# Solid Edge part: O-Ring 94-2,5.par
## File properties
Title: O-Ring 94-2,5
Author: Dan
Template: Normal Colour.par
Last saved by: Dan
Revision: 9
Application: Solid Edge
Density: 0 kg/mm^3
Accuracy: 0.99
Document Number: P52-009
Project Name: Piston Pump P52
Material: nitrile
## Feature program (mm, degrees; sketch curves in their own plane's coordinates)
sketch for "unnamed RevolvedProtrusion 1" plane through (0, 0, 0) normal (0, 0, 1) x-axis (1, 0, 0)
  circle centre (0, -48.25) radius 1.25
revolve "unnamed RevolvedProtrusion 1" add finite 360 deg
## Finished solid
Body 1: solid body, 1 face, 0 edges, 0 vertices.
  Faces by surface: torus 1
Toroidal faces (ring radius, tube radius in mm): R48.25 r1.25 x1
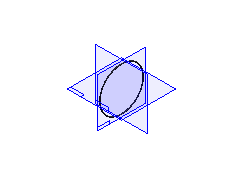
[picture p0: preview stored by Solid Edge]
